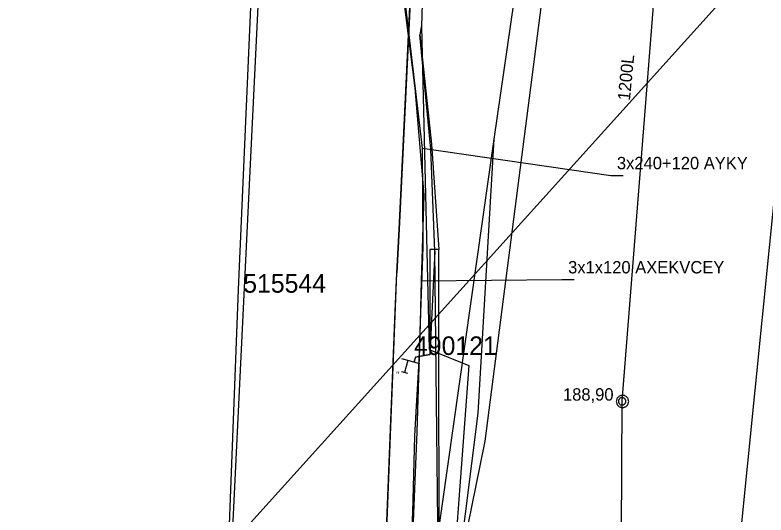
# Model space of a CAD drawing. Extents: x -746464 to -745690, y -1051581 to -1049993.
# Drawn here: x -745881.4 to -745820.6, y -1050975.5 to -1050935.1 of the extents above; entities that cross this region are included whole.
import ezdxf

# ---------------------------------------------------------------- set-up
doc = ezdxf.new("R2010")
doc.units = 0
for name, color, linetype in [('04_CETIN_neprovozovane', 7, 'Continuous'), ('04_CETIN_radiove site', 7, 'Continuous'), ('04_CETIN_sdelovaci_podzem', 7, 'Continuous'), ('45_Eltodo_popisy', 7, 'Continuous'), ('45_Eltodo_vedeni_NN_zemni', 7, 'Continuous'), ('51_PVaK_kanal_jednotna_overena poloha_rad', 7, 'Continuous'), ('51_PVaK_kanal_objekty', 7, 'Continuous'), ('51_PVaK_kanal_popisy', 7, 'Continuous'), ('51_PVaK_vodovod_NEPROVOZUJE PVK_neoverene poloha', 7, 'Continuous'), ('55_PREdi_NN', 7, 'Continuous'), ('55_PREdi_NN_popisy', 7, 'Continuous'), ('55_PREdi_NN_pripojovaci_misto', 7, 'Continuous'), ('55_PREdi_VN', 7, 'Continuous'), ('55_PREdi_VN_popisy', 7, 'Continuous'), ('55_PREdi_ZRUSENE_elektro', 7, 'Continuous'), ('57_TSK Praha_sdelovaci_optika_orientacni poloha', 7, 'Continuous')]:
    doc.layers.add(name, color=color, linetype=linetype)

msp = doc.modelspace()

# ---------------------------------------------------------------- linework, layer by layer
at = {"layer": '04_CETIN_neprovozovane'}
for points in [[(-745842.63, -1050945.15), (-745837.51, -1050909.78), (-745831.68, -1050857.42)], [(-745843.36, -1050969.55), (-745836.71, -1050917.96)], [(-745849.04, -1050997.55), (-745848.23, -1050984.71), (-745842.63, -1050945.15)], [(-745849.04, -1050997.55), (-745843.36, -1050969.55)]]:
    msp.add_lwpolyline(points, dxfattribs=at)
at = {"layer": '04_CETIN_radiove site'}
msp.add_line((-745690.053, -1050785.364), (-746408.207, -1051580.571), dxfattribs=at)
at = {"layer": '04_CETIN_sdelovaci_podzem'}
for points in [[(-745798.39, -1050529.48), (-745804.32, -1050569.6), (-745807.29, -1050589.25), (-745813.21, -1050629.8), (-745816.05, -1050649.15), (-745817.02, -1050656.79), (-745822.46, -1050693.51), (-745829.82, -1050740.58), (-745836.65, -1050788.06), (-745842.43, -1050837.27), (-745847.37, -1050897.12), (-745848.5, -1050936.02), (-745847.9, -1050962.15), (-745844.68, -1050963.44), (-745846.49, -1050987.64)], [(-745846.49, -1050987.64), (-745843.93, -1050967.29), (-745842.63, -1050945.15)]]:
    msp.add_lwpolyline(points, dxfattribs=at)
at = {"layer": '45_Eltodo_vedeni_NN_zemni'}
for points in [[(-745863.32, -1050957.28), (-745862.27, -1050933.2), (-745861.22, -1050909.12)], [(-745847.44, -1050954.179), (-745847.83, -1050962.57), (-745849.03, -1050962.78), (-745849.109, -1050963.169)], [(-745865.14, -1051005.19), (-745864.23, -1050981.235), (-745863.32, -1050957.28)]]:
    msp.add_lwpolyline(points, dxfattribs=at)
at = {"layer": '51_PVaK_kanal_jednotna_overena poloha_rad'}
for p, q in [((-745832.28, -1050966.33), (-745828.24, -1050915.62)), ((-745832.53, -1051010.62), (-745832.28, -1050966.33))]:
    msp.add_line(p, q, dxfattribs=at)
at = {"layer": '51_PVaK_kanal_objekty'}
for points in [[(-745831.75, -1050966.34), (-745831.76, -1050966.29), (-745831.76, -1050966.24), (-745831.78, -1050966.19), (-745831.8, -1050966.14), (-745831.82, -1050966.09), (-745831.85, -1050966.05), (-745831.88, -1050966.01), (-745831.92, -1050965.97), (-745831.96, -1050965.94), (-745832, -1050965.91), (-745832.05, -1050965.89), (-745832.1, -1050965.87), (-745832.15, -1050965.85), (-745832.2, -1050965.85), (-745832.25, -1050965.84), (-745832.3, -1050965.85), (-745832.35, -1050965.85), (-745832.4, -1050965.87), (-745832.45, -1050965.89), (-745832.5, -1050965.91), (-745832.54, -1050965.94), (-745832.58, -1050965.97), (-745832.62, -1050966.01), (-745832.65, -1050966.05), (-745832.68, -1050966.09), (-745832.7, -1050966.14), (-745832.72, -1050966.19), (-745832.74, -1050966.24), (-745832.74, -1050966.29), (-745832.75, -1050966.34), (-745832.74, -1050966.39), (-745832.74, -1050966.44), (-745832.72, -1050966.49), (-745832.7, -1050966.54), (-745832.68, -1050966.59), (-745832.65, -1050966.63), (-745832.62, -1050966.67), (-745832.58, -1050966.71), (-745832.54, -1050966.74), (-745832.5, -1050966.77), (-745832.45, -1050966.79), (-745832.4, -1050966.81), (-745832.35, -1050966.83), (-745832.3, -1050966.83), (-745832.25, -1050966.84), (-745832.2, -1050966.83), (-745832.15, -1050966.83), (-745832.1, -1050966.81), (-745832.05, -1050966.79), (-745832, -1050966.77), (-745831.96, -1050966.74), (-745831.92, -1050966.71), (-745831.88, -1050966.67), (-745831.85, -1050966.63), (-745831.82, -1050966.59), (-745831.8, -1050966.54), (-745831.78, -1050966.49), (-745831.76, -1050966.44), (-745831.76, -1050966.39), (-745831.75, -1050966.34)], [(-745831.98, -1050966.33), (-745831.98, -1050966.3), (-745831.986, -1050966.27), (-745831.992, -1050966.24), (-745832.004, -1050966.21), (-745832.022, -1050966.18), (-745832.04, -1050966.156), (-745832.058, -1050966.132), (-745832.082, -1050966.108), (-745832.106, -1050966.09), (-745832.13, -1050966.072), (-745832.16, -1050966.054), (-745832.19, -1050966.042), (-745832.22, -1050966.036), (-745832.25, -1050966.03), (-745832.28, -1050966.03), (-745832.31, -1050966.03), (-745832.34, -1050966.036), (-745832.37, -1050966.042), (-745832.4, -1050966.054), (-745832.43, -1050966.072), (-745832.454, -1050966.09), (-745832.478, -1050966.108), (-745832.502, -1050966.132), (-745832.52, -1050966.156), (-745832.538, -1050966.18), (-745832.556, -1050966.21), (-745832.568, -1050966.24), (-745832.574, -1050966.27), (-745832.58, -1050966.3), (-745832.58, -1050966.33), (-745832.58, -1050966.36), (-745832.574, -1050966.39), (-745832.568, -1050966.42), (-745832.556, -1050966.45), (-745832.538, -1050966.48), (-745832.52, -1050966.504), (-745832.502, -1050966.528), (-745832.478, -1050966.552), (-745832.454, -1050966.57), (-745832.43, -1050966.588), (-745832.4, -1050966.606), (-745832.37, -1050966.618), (-745832.34, -1050966.624), (-745832.31, -1050966.63), (-745832.28, -1050966.63), (-745832.25, -1050966.63), (-745832.22, -1050966.624), (-745832.19, -1050966.618), (-745832.16, -1050966.606), (-745832.13, -1050966.588), (-745832.106, -1050966.57), (-745832.082, -1050966.552), (-745832.058, -1050966.528), (-745832.04, -1050966.504), (-745832.022, -1050966.48), (-745832.004, -1050966.45), (-745831.992, -1050966.42), (-745831.986, -1050966.39), (-745831.98, -1050966.36), (-745831.98, -1050966.33)]]:
    msp.add_lwpolyline(points, dxfattribs=at)
at = {"layer": '51_PVaK_vodovod_NEPROVOZUJE PVK_neoverene poloha'}
msp.add_line((-745828.479, -1051034.728), (-745784.302, -1050594.304), dxfattribs=at)
at = {"layer": '55_PREdi_NN'}
for points in [[(-745841.068, -1050996.415), (-745841.055, -1050997.599), (-745846.823, -1050996.637), (-745847.22, -1050996.09), (-745849.35, -1050995.52), (-745849.98, -1050995.09), (-745850.02, -1050994.63), (-745849.64, -1050986.23), (-745849.18, -1050976.72), (-745848.85, -1050968.79), (-745848.535, -1050958.295), (-745848.37, -1050953.87), (-745848.44, -1050945.87), (-745849.34, -1050938.08), (-745850.24, -1050930.51)], [(-745838.36, -1050996.99), (-745838.5, -1050997.65), (-745838.89, -1050997.81), (-745839.99, -1050997.37), (-745840.82, -1050997.29), (-745841.69, -1050997.3), (-745845.06, -1050996.47), (-745846.38, -1050996.33), (-745848.06, -1050995.85), (-745849.35, -1050995.52), (-745849.98, -1050995.09), (-745850.02, -1050994.63), (-745849.64, -1050986.23), (-745849.18, -1050976.72), (-745848.85, -1050968.79), (-745848.678, -1050962.132), (-745848.37, -1050953.87), (-745848.44, -1050945.87), (-745849.34, -1050938.08), (-745850.24, -1050930.51)], [(-745848.54, -1050936.06), (-745848.65, -1050936.71)], [(-745848.65, -1050936.71), (-745847.7, -1050945.552), (-745847.102, -1050954.051)], [(-745839.088, -1050998.723), (-745842.824, -1050997.149), (-745845.785, -1050996.81), (-745846.546, -1050991.646), (-745847.075, -1050985.822), (-745847.44, -1050954.179), (-745847.766, -1050945.949), (-745848.65, -1050936.71)], [(-745847.102, -1050954.051), (-745847.829, -1050954.069), (-745847.837, -1050962.555), (-745849.007, -1050962.755), (-745849.13, -1050963.171)], [(-745847.44, -1050954.179), (-745847.83, -1050962.57), (-745849.03, -1050962.78), (-745849.109, -1050963.169)], [(-745842.001, -1050995.642), (-745842.068, -1050996.426), (-745842.771, -1050996.304), (-745843.825, -1050996.126), (-745845.908, -1050995.766), (-745847.075, -1050985.822), (-745847.102, -1050954.051)], [(-745848.65, -1050963.313), (-745849.13, -1050963.171), (-745849.609, -1050963.029), (-745850.089, -1050962.887)], [(-745849.609, -1050963.029), (-745849.751, -1050963.509)]]:
    msp.add_lwpolyline(points, dxfattribs=at)
at = {"layer": '55_PREdi_NN_popisy'}
msp.add_lwpolyline([(-745848.44, -1050945.87), (-745833.203, -1050948.069), (-745832.203, -1050948.069)], dxfattribs=at)
at = {"layer": '55_PREdi_NN_pripojovaci_misto'}
for p, q in [((-745849.751, -1050963.509), (-745849.889, -1050963.99)), ((-745850.129, -1050963.921), (-745849.649, -1050964.059))]:
    msp.add_line(p, q, dxfattribs=at)
at = {"layer": '55_PREdi_VN'}
for points in [[(-745850.17, -1050932.07), (-745849.05, -1050941.01), (-745848.32, -1050949.64), (-745848.53, -1050956.59), (-745848.68, -1050962.14), (-745848.96, -1050967.17), (-745849.07, -1050969.15), (-745849.24, -1050975.31), (-745849.73, -1050985.83), (-745850.18, -1050993.28), (-745849.92, -1050994.71), (-745849.29, -1050995.47), (-745848.52, -1050995.83), (-745845.77, -1050996.5), (-745843.945, -1050996.995), (-745841.33, -1050997.69), (-745840.89, -1050997.42), (-745838.156, -1050991.392)], [(-745850.17, -1050932.07), (-745849.05, -1050941.01), (-745848.32, -1050949.64), (-745848.53, -1050956.59), (-745848.68, -1050962.14), (-745848.96, -1050967.17), (-745849.07, -1050969.15), (-745849.24, -1050975.31), (-745849.73, -1050985.83), (-745850.18, -1050993.28), (-745849.92, -1050994.71), (-745849.29, -1050995.47), (-745848.52, -1050995.83), (-745845.77, -1050996.5), (-745842.12, -1050997.49), (-745841.33, -1050997.69), (-745840.89, -1050997.42), (-745840.61, -1050996.53)], [(-745850.298, -1050951.869), (-745850.496, -1050955.948)], [(-745851.722, -1050989.479), (-745851.786, -1050989.154), (-745851.428, -1050978.754), (-745850.647, -1050959.06), (-745850.496, -1050955.948)]]:
    msp.add_lwpolyline(points, dxfattribs=at)
at = {"layer": '55_PREdi_VN_popisy'}
msp.add_lwpolyline([(-745848.53, -1050956.59), (-745837.15, -1050956.49), (-745836.15, -1050956.49)], dxfattribs=at)
at = {"layer": '55_PREdi_ZRUSENE_elektro'}
for points in [[(-745850.635, -1050992.876), (-745851.513, -1050992.881), (-745851.444, -1050990.883), (-745851.607, -1050990.028), (-745851.786, -1050989.154), (-745850.496, -1050955.948), (-745850.298, -1050951.869), (-745849.152, -1050928.242), (-745848.006, -1050904.616), (-745845.662, -1050869.668), (-745842.994, -1050839.781), (-745842.166, -1050839.684), (-745841.651, -1050839.662), (-745841.138, -1050839.47), (-745840.785, -1050838.976), (-745840.919, -1050838.371), (-745841.417, -1050838.108), (-745843.594, -1050837.764)], [(-745843.249, -1050837.823), (-745841.174, -1050838.15), (-745840.919, -1050838.371), (-745840.789, -1050838.776), (-745840.847, -1050839.152), (-745841.138, -1050839.47), (-745841.651, -1050839.662), (-745842.681, -1050839.706), (-745842.933, -1050839.768), (-745843.021, -1050839.857), (-745845.662, -1050869.668), (-745848.006, -1050904.616), (-745850.298, -1050951.869)]]:
    msp.add_lwpolyline(points, dxfattribs=at)
at = {"layer": '57_TSK Praha_sdelovaci_optika_orientacni poloha'}
msp.add_lwpolyline([(-745866.915, -1051055.215), (-745864.415, -1050989.902), (-745858.085, -1050859.426), (-745851.786, -1050798.238)], dxfattribs=at)

# ---------------------------------------------------------------- texts
at = {"layer": '45_Eltodo_popisy'}
for s, p in [('515544', (-745862.927, -1050957.549)), ('490121', (-745849.111, -1050962.584))]:
    msp.add_text(s, height=1.5, dxfattribs=at).set_placement(p)
at = {"layer": '51_PVaK_kanal_popisy'}
msp.add_text('1200L', height=1, rotation=84.44419, dxfattribs=at).set_placement((-745831.653, -1050942.051))
msp.add_text('188,90', height=1, dxfattribs=at).set_placement((-745837.065, -1050966.276))
at = {"layer": '55_PREdi_NN_popisy'}
msp.add_text('3x240+120 AYKY', height=1, dxfattribs=at).set_placement((-745832.703, -1050947.569))
at = {"layer": '55_PREdi_NN_pripojovaci_misto'}
msp.add_text('M', height=0.2, rotation=164, dxfattribs=at).set_placement((-745850.287, -1050963.927))
at = {"layer": '55_PREdi_VN_popisy'}
msp.add_text('3x1x120 AXEKVCEY', height=1, dxfattribs=at).set_placement((-745836.65, -1050955.99))

doc.saveas('drawing.dxf')
